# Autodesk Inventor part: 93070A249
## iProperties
Created: 2010-11
Part Number: 93070A249
Document SubType Name: Modeling
Designer: Administrator
Density: 7.85 g/cm^3
Material: Steel
Mass: 43.046 g
Surface Area: 30.654 cm^2
Volume: 5.48356 cm^3
Translation Standard: STEP AP203
FileName: 93070A249.step
PreProcessor: SolidWorks 2003314
PostProcessor: Build: 236a, Release: 2009 RTM - Date: Fri 02/22/2008
Sent Units: MM
Uncertainty: 1e-05
Author: Administrator
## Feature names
1. Base1
